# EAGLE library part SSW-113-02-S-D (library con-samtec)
THROUGH-HOLE .025" SQ POST SOCKET Source: Samtec SSW.pdf
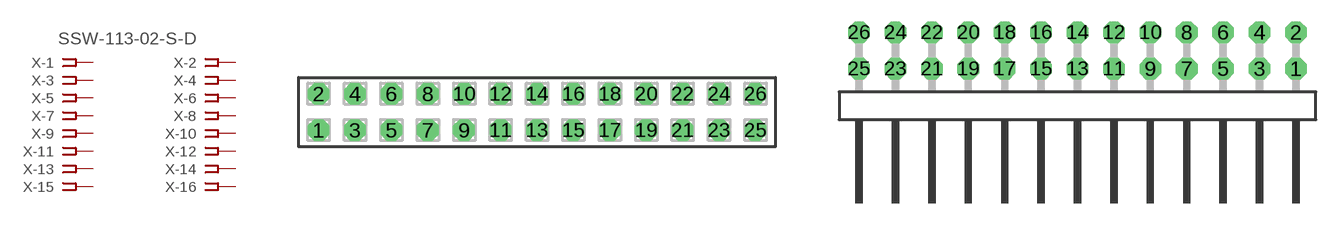
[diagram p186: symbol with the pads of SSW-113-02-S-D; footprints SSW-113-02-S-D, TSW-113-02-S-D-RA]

Designator prefix X; gates -1=FPINV -2=FPIN -3=FPIN -4=FPIN -5=FPIN -6=FPIN -7=FPIN -8=FPIN -9=FPIN -10=FPIN -11=FPIN -12=FPIN -13=FPIN -14=FPIN -15=FPIN -16=FPIN -17=FPIN -18=FPIN -19=FPIN -20=FPIN -21=FPIN -22=FPIN -23=FPIN -24=FPIN -25=FPIN -26=FPIN

## SSW-113-02-S-D (MPN: SSW-113-02-S-D; OC_FARNELL: unknown; OC_NEWARK: 11P9530)  [SSW-113-02-S-D]
1  -1:1  pas
2  -2:1  pas
3  -3:1  pas
4  -4:1  pas
5  -5:1  pas
6  -6:1  pas
7  -7:1  pas
8  -8:1  pas
9  -9:1  pas
10  -10:1  pas
11  -11:1  pas
12  -12:1  pas
13  -13:1  pas
14  -14:1  pas
15  -15:1  pas
16  -16:1  pas
17  -17:1  pas
18  -18:1  pas
19  -19:1  pas
20  -20:1  pas
21  -21:1  pas
22  -22:1  pas
23  -23:1  pas
24  -24:1  pas
25  -25:1  pas
26  -26:1  pas

## SSW-113-02-S-D-RA (MPN: SSW-113-02-S-D-RA; OC_FARNELL: unknown; OC_NEWARK: 11P9531)  [TSW-113-02-S-D-RA]
Pads as for SSW-113-02-S-D

## Footprint SSW-113-02-S-D (pad centres in mm)
THROUGH-HOLE .025" SQ POST SOCKET Source: Samtec SSW.pdf
drill 1 pad 1.5 octagon: 1 -15.24,-1.27; 2 -15.24,1.27; 3 -12.7,-1.27; 4 -12.7,1.27; 5 -10.16,-1.27; 6 -10.16,1.27; 7 -7.62,-1.27; 8 -7.62,1.27; 9 -5.08,-1.27; 10 -5.08,1.27; 11 -2.54,-1.27; 12 -2.54,1.27; 13 0,-1.27; 14 0,1.27; 15 2.54,-1.27; 16 2.54,1.27; 17 5.08,-1.27; 18 5.08,1.27; 19 7.62,-1.27; 20 7.62,1.27; 21 10.16,-1.27; 22 10.16,1.27; 23 12.7,-1.27; 24 12.7,1.27; 25 15.24,-1.27; 26 15.24,1.27

## Footprint TSW-113-02-S-D-RA (pad centres in mm)
THROUGH-HOLE .025" SQ POST HEADER Source: Samtec TSW.pdf
drill 1 pad 1.5 octagon: 1 15.24,1.524; 2 15.24,4.064; 3 12.7,1.524; 4 12.7,4.064; 5 10.16,1.524; 6 10.16,4.064; 7 7.62,1.524; 8 7.62,4.064; 9 5.08,1.524; 10 5.08,4.064; 11 2.54,1.524; 12 2.54,4.064; 13 0,1.524; 14 0,4.064; 15 -2.54,1.524; 16 -2.54,4.064; 17 -5.08,1.524; 18 -5.08,4.064; 19 -7.62,1.524; 20 -7.62,4.064; 21 -10.16,1.524; 22 -10.16,4.064; 23 -12.7,1.524; 24 -12.7,4.064; 25 -15.24,1.524; 26 -15.24,4.064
